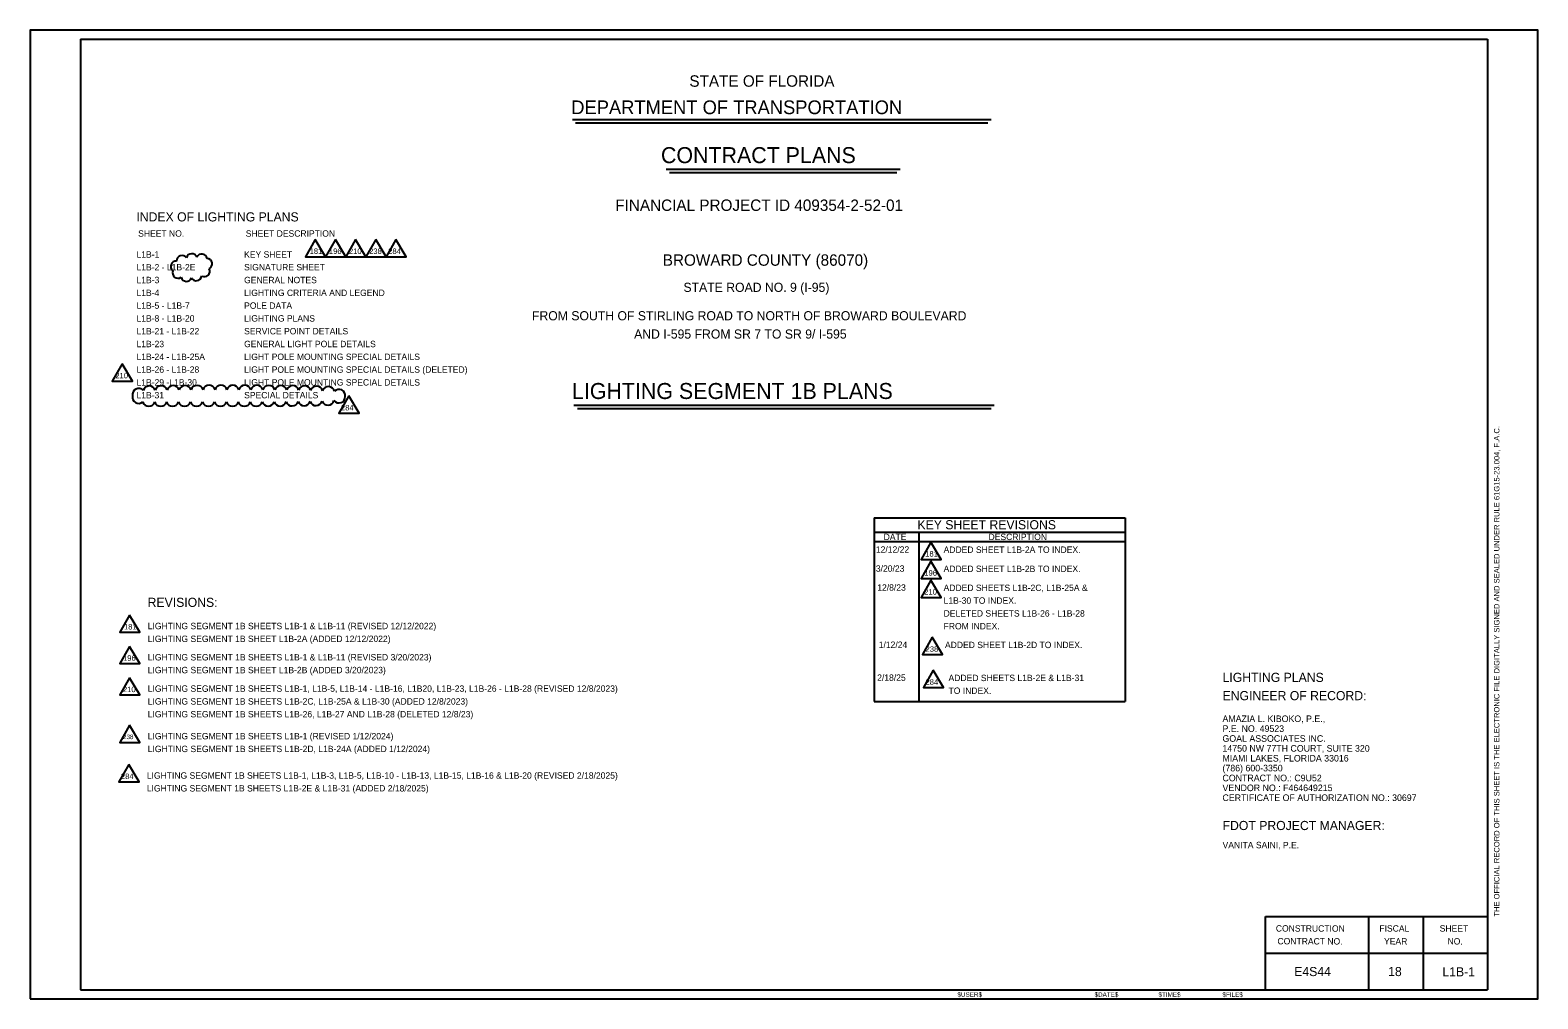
# Model space of a CAD drawing. Extents: x -818.6 to -802.1, y -2197.9 to -2175.
# Drawn here: x -818.56 to -802.06, y -2197.92 to -2187.32 of the extents above; entities that cross this region are included whole.
import ezdxf

# ---------------------------------------------------------------- set-up
doc = ezdxf.new("R2010")
doc.units = 0
for name, color, linetype in [('ActivePointCell_dp', 7, 'Continuous'), ('Cloud_dp', 7, 'Continuous'), ('PlotBorder_dp', 7, 'Continuous'), ('SheetBorder_dp', 7, 'Continuous'), ('SheetLines_dp', 7, 'Continuous'), ('SumBoxLines_dp', 7, 'Continuous'), ('TextLabel', 7, 'Continuous'), ('TextMinor', 7, 'Continuous'), ('TextMisc', 7, 'Continuous'), ('TextNotes', 7, 'Continuous'), ('TextShtNo', 7, 'Continuous'), ('TextTitle', 7, 'Continuous')]:
    doc.layers.add(name, color=color, linetype=linetype)

msp = doc.modelspace()

# ---------------------------------------------------------------- linework, layer by layer
at = {"layer": 'ActivePointCell_dp'}
msp.add_line((-802.614, -2187.419), (-802.614, -2187.419), dxfattribs=at)
at = {"layer": 'Cloud_dp'}
for points in [[(-815.443, -2189.61), (-815.551, -2189.798), (-815.33, -2189.798)], [(-815.222, -2189.61), (-815.33, -2189.798), (-815.109, -2189.798)], [(-815.002, -2189.61), (-815.109, -2189.798), (-814.889, -2189.798)], [(-814.781, -2189.61), (-814.889, -2189.798), (-814.668, -2189.798)], [(-814.56, -2189.61), (-814.667, -2189.798), (-814.447, -2189.798)], [(-817.558, -2190.971), (-817.666, -2191.159), (-817.445, -2191.159)], [(-815.076, -2191.322), (-815.184, -2191.51), (-814.963, -2191.51)], [(-808.706, -2192.922), (-808.814, -2193.11), (-808.593, -2193.11)], [(-808.706, -2193.13), (-808.814, -2193.318), (-808.593, -2193.318)], [(-808.706, -2193.338), (-808.814, -2193.526), (-808.593, -2193.526)], [(-817.475, -2193.719), (-817.583, -2193.907), (-817.362, -2193.907)], [(-808.691, -2193.963), (-808.799, -2194.151), (-808.578, -2194.151)], [(-817.475, -2194.062), (-817.583, -2194.25), (-817.362, -2194.25)], [(-808.68, -2194.324), (-808.787, -2194.512), (-808.567, -2194.512)], [(-817.475, -2194.405), (-817.583, -2194.593), (-817.362, -2194.593)], [(-817.475, -2194.924), (-817.583, -2195.113), (-817.362, -2195.113)], [(-817.485, -2195.356), (-817.593, -2195.544), (-817.372, -2195.544)]]:
    msp.add_lwpolyline(points, close=True, dxfattribs=at)
for centre, radius, start, end in [((-816.966, -2189.905), 0.0599, 86.9907, 231.9907), ((-816.902, -2189.845), 0.06, 35.4166, 180.4166), ((-816.795, -2189.825), 0.0599, 21.2778, 166.2778), ((-816.685, -2189.828), 0.0599, 9.9863, 154.9863), ((-816.632, -2189.877), 0.0599, 298.9542, 83.9542), ((-816.946, -2189.974), 0.0599, 159.4236, 304.4236), ((-816.854, -2190.008), 0.0599, 194.4381, 339.4381), ((-816.745, -2190.001), 0.0599, 207.5787, 352.5787), ((-816.657, -2189.957), 0.0599, 241.4449, 26.4449), ((-817.377, -2191.335), 0.0686, 166.4751, 311.4751), ((-817.376, -2191.309), 0.0686, 43.0695, 188.0695), ((-817.26, -2191.281), 0.0686, 19.0384, 164.0384), ((-817.129, -2191.278), 0.0686, 18.4168, 163.4168), ((-816.999, -2191.277), 0.0686, 18.1078, 163.1078), ((-816.868, -2191.276), 0.0686, 17.9137, 162.9137), ((-816.737, -2191.275), 0.0686, 17.7772, 162.7772), ((-816.606, -2191.274), 0.0686, 17.6744, 162.6744), ((-816.475, -2191.274), 0.0686, 17.5934, 162.5934), ((-816.345, -2191.274), 0.0686, 17.5274, 162.5274), ((-816.214, -2191.274), 0.0686, 17.4419, 162.4419), ((-816.083, -2191.274), 0.0686, 17.3173, 162.3173), ((-815.952, -2191.275), 0.0686, 17.164, 162.164), ((-815.821, -2191.276), 0.0686, 16.9692, 161.9692), ((-815.691, -2191.277), 0.0686, 16.7096, 161.7096), ((-815.56, -2191.279), 0.0686, 16.3389, 161.3389), ((-815.429, -2191.283), 0.0686, 15.744, 160.744), ((-815.299, -2191.288), 0.0686, 14.5241, 159.5241), ((-815.184, -2191.33), 0.0687, 217.023, 2.023), ((-815.183, -2191.318), 0.0685, 351.6834, 136.6834), ((-817.266, -2191.366), 0.0686, 197.5, 342.5), ((-817.135, -2191.366), 0.0686, 197.5, 342.5), ((-817.005, -2191.366), 0.0686, 197.5, 342.5), ((-816.874, -2191.366), 0.0686, 197.5, 342.5), ((-816.743, -2191.366), 0.0686, 197.5, 342.5), ((-816.612, -2191.366), 0.0686, 197.5, 342.5), ((-816.481, -2191.366), 0.0686, 197.5, 342.5), ((-816.35, -2191.366), 0.0686, 197.5, 342.5), ((-816.22, -2191.366), 0.0686, 197.5078, 342.5078), ((-816.089, -2191.366), 0.0686, 197.6006, 342.6006), ((-815.958, -2191.365), 0.0686, 197.7378, 342.7378), ((-815.827, -2191.364), 0.0686, 197.9119, 342.9119), ((-815.696, -2191.363), 0.0686, 198.1433, 343.1433), ((-815.566, -2191.361), 0.0686, 198.4725, 343.4725), ((-815.435, -2191.359), 0.0686, 198.9973, 343.9973), ((-815.305, -2191.354), 0.0686, 200.0559, 345.0559)]:
    msp.add_arc(centre, radius, start, end, dxfattribs=at)
at = {"layer": 'PlotBorder_dp'}
msp.add_lwpolyline([(-818.564, -2197.919), (-802.064, -2197.919), (-802.064, -2187.319), (-818.564, -2187.319)], close=True, dxfattribs=at)
at = {"layer": 'SheetBorder_dp'}
for p, q in [((-818.014, -2187.419), (-818.014, -2197.819)), ((-818.014, -2187.419), (-802.614, -2187.419)), ((-802.614, -2187.419), (-802.614, -2197.819)), ((-818.014, -2197.819), (-802.614, -2197.819))]:
    msp.add_line(p, q, dxfattribs=at)
at = {"layer": 'SheetLines_dp'}
for p, q in [((-805.044, -2197.019), (-802.614, -2197.019)), ((-805.044, -2197.819), (-805.044, -2197.019)), ((-803.914, -2197.819), (-803.914, -2197.019)), ((-803.314, -2197.819), (-803.314, -2197.019)), ((-805.044, -2197.419), (-802.614, -2197.419))]:
    msp.add_line(p, q, dxfattribs=at)
at = {"layer": 'SumBoxLines_dp'}
for p, q in [((-809.327, -2192.654), (-809.327, -2194.666)), ((-809.327, -2192.654), (-806.58, -2192.654)), ((-806.58, -2192.654), (-806.58, -2194.666)), ((-809.327, -2192.814), (-806.58, -2192.814)), ((-808.837, -2192.814), (-808.837, -2194.666)), ((-809.327, -2192.914), (-806.58, -2192.914)), ((-809.327, -2194.666), (-806.58, -2194.666))]:
    msp.add_line(p, q, dxfattribs=at)
at = {"layer": 'TextTitle'}
for p, q in [((-812.63, -2188.295), (-808.048, -2188.295)), ((-812.597, -2188.333), (-808.083, -2188.333)), ((-811.605, -2188.84), (-809.044, -2188.84)), ((-811.566, -2188.878), (-809.077, -2188.878)), ((-812.614, -2191.421), (-808.015, -2191.421)), ((-812.575, -2191.459), (-808.047, -2191.459))]:
    msp.add_line(p, q, dxfattribs=at)

# ---------------------------------------------------------------- texts
at = {"layer": 'Cloud_dp'}
for s, height, p in [('181', 0.06, (-815.505, -2189.768)), ('196', 0.06, (-815.294, -2189.768)), ('210', 0.06, (-815.075, -2189.768)), ('238', 0.06, (-814.854, -2189.768)), ('284', 0.06, (-814.645, -2189.768)), ('210', 0.06, (-817.631, -2191.129)), ('284', 0.06, (-815.162, -2191.48)), ('181', 0.06, (-808.768, -2193.079)), ('196', 0.06, (-808.778, -2193.288)), ('210', 0.06, (-808.779, -2193.496)), ('181', 0.06, (-817.537, -2193.877)), ('196', 0.06, (-817.547, -2194.22)), ('238', 0.06, (-808.764, -2194.121)), ('284', 0.06, (-808.765, -2194.482)), ('210', 0.06, (-817.548, -2194.563)), ('238', 0.05, (-817.548, -2195.077)), ('284', 0.06, (-817.57, -2195.514))]:
    msp.add_text(s, height=height, rotation=0, dxfattribs=at).set_placement(p)
at = {"layer": 'TextLabel'}
for s, height, p in [('FINANCIAL PROJECT ID 409354-2-52-01', 0.125, (-812.16, -2189.297)), ('INDEX OF LIGHTING PLANS', 0.1, (-817.401, -2189.412)), ('L1B-1', 0.07, (-817.4, -2189.808)), ('L1B-2 - L1B-2E', 0.07, (-817.4, -2189.948)), ('SIGNATURE SHEET', 0.07, (-816.222, -2189.948)), ('KEY SHEET', 0.07, (-816.222, -2189.808)), ('BROWARD COUNTY (86070)', 0.125, (-811.64, -2189.897)), ('L1B-3', 0.07, (-817.4, -2190.088)), ('GENERAL NOTES', 0.07, (-816.222, -2190.088)), ('L1B-4', 0.07, (-817.4, -2190.228)), ('LIGHTING CRITERIA AND LEGEND', 0.07, (-816.222, -2190.228)), ('STATE ROAD NO. 9 (I-95)', 0.1, (-811.414, -2190.183)), ('L1B-5 - L1B-7', 0.07, (-817.4, -2190.368)), ('POLE DATA', 0.07, (-816.222, -2190.368)), ('L1B-8 - L1B-20', 0.07, (-817.4, -2190.508)), ('LIGHTING PLANS', 0.07, (-816.222, -2190.508)), ('FROM SOUTH OF STIRLING ROAD TO NORTH OF BROWARD BOULEVARD', 0.1, (-813.072, -2190.494)), ('L1B-21 - L1B-22', 0.07, (-817.4, -2190.648)), ('SERVICE POINT DETAILS', 0.07, (-816.222, -2190.648)), ('AND I-595 FROM SR 7 TO SR 9/ I-595', 0.1, (-811.954, -2190.694)), ('L1B-23', 0.07, (-817.4, -2190.788)), ('L1B-24 - L1B-25A', 0.07, (-817.4, -2190.928)), ('GENERAL LIGHT POLE DETAILS', 0.07, (-816.222, -2190.788)), ('LIGHT POLE MOUNTING SPECIAL DETAILS', 0.07, (-816.222, -2190.928)), ('L1B-26 - L1B-28', 0.07, (-817.4, -2191.068)), ('LIGHT POLE MOUNTING SPECIAL DETAILS (DELETED)', 0.07, (-816.222, -2191.068)), ('L1B-29 -L1B-30', 0.07, (-817.4, -2191.208)), ('LIGHT POLE MOUNTING SPECIAL DETAILS', 0.07, (-816.222, -2191.208)), ('L1B-31', 0.07, (-817.4, -2191.348)), ('SPECIAL DETAILS', 0.07, (-816.222, -2191.348)), ('KEY SHEET REVISIONS', 0.1, (-808.853, -2192.781)), ('REVISIONS:', 0.1, (-817.278, -2193.63)), ('LIGHTING PLANS', 0.1, (-805.514, -2194.451)), ('ENGINEER OF RECORD:', 0.1, (-805.514, -2194.651)), ('AMAZIA L. KIBOKO, P.E.,', 0.07202, (-805.515, -2194.89)), ('P.E. NO. 49523', 0.07202, (-805.515, -2194.998)), ('GOAL ASSOCIATES INC. ', 0.07202, (-805.515, -2195.106)), ('14750 NW 77TH COURT, SUITE 320', 0.07202, (-805.515, -2195.214)), ('MIAMI LAKES, FLORIDA 33016', 0.07202, (-805.515, -2195.322)), ('CONTRACT NO.: C9U52', 0.07202, (-805.515, -2195.538)), ('(786) 600-3350', 0.07202, (-805.515, -2195.43)), ('VENDOR NO.: F464649215', 0.07202, (-805.515, -2195.646)), ('CERTIFICATE OF AUTHORIZATION NO.: 30697', 0.07202, (-805.515, -2195.754)), ('E4S44', 0.1, (-804.73, -2197.67)), ('18', 0.1, (-803.702, -2197.67))]:
    msp.add_text(s, height=height, dxfattribs=at).set_placement(p)
at = {"layer": 'TextMinor'}
for s, height, p in [('12/12/22', 0.07, (-809.308, -2193.037)), ('ADDED SHEET L1B-2A TO INDEX.', 0.07, (-808.567, -2193.039)), ('3/20/23', 0.07, (-809.308, -2193.245)), ('ADDED SHEET L1B-2B TO INDEX.', 0.07, (-808.567, -2193.248)), ('12/8/23', 0.07, (-809.293, -2193.453)), ('ADDED SHEETS L1B-2C, L1B-25A & ', 0.07, (-808.567, -2193.456)), ('L1B-30 TO INDEX.', 0.07, (-808.567, -2193.596)), ('DELETED SHEETS L1B-26 - L1B-28 ', 0.07, (-808.567, -2193.736)), ('FROM INDEX.', 0.07, (-808.567, -2193.876)), ('1/12/24', 0.07, (-809.277, -2194.079)), ('ADDED SHEET L1B-2D TO INDEX.', 0.07, (-808.552, -2194.081)), ('2/18/25', 0.07, (-809.294, -2194.439)), ('ADDED SHEETS L1B-2E & L1B-31   ', 0.07, (-808.513, -2194.442)), ('TO INDEX.', 0.07, (-808.513, -2194.582)), ('$USER$', 0.05, (-808.415, -2197.897))]:
    msp.add_text(s, height=height, dxfattribs=at).set_placement(p)
for s, p in [('$DATE$', (-806.915, -2197.897)), ('$TIME$', (-806.215, -2197.897)), ('$FILE$', (-805.515, -2197.897))]:
    msp.add_text(s, height=0.05, rotation=360, dxfattribs=at).set_placement(p)
at = {"layer": 'TextMisc'}
msp.add_text('THE OFFICIAL RECORD OF THIS SHEET IS THE ELECTRONIC FILE DIGITALLY SIGNED AND SEALED UNDER RULE 61G15-23.004, F.A.C.', height=0.06, rotation=90, dxfattribs=at).set_placement((-802.484, -2197.019))
at = {"layer": 'TextNotes'}
for s, height, p in [('SHEET NO.', 0.07, (-817.382, -2189.579)), ('SHEET DESCRIPTION', 0.07, (-816.204, -2189.579)), ('DATE', 0.07, (-809.223, -2192.899)), ('DESCRIPTION', 0.07, (-808.075, -2192.899)), ('LIGHTING SEGMENT 1B SHEETS L1B-1 & L1B-11 (REVISED 12/12/2022)', 0.06998, (-817.277, -2193.874)), ('LIGHTING SEGMENT 1B SHEET L1B-2A (ADDED 12/12/2022)', 0.06998, (-817.277, -2194.014)), ('LIGHTING SEGMENT 1B SHEETS L1B-1 & L1B-11 (REVISED 3/20/2023)', 0.06998, (-817.277, -2194.216)), ('LIGHTING SEGMENT 1B SHEET L1B-2B (ADDED 3/20/2023)', 0.06998, (-817.277, -2194.356)), ('LIGHTING SEGMENT 1B SHEETS L1B-1, L1B-5, L1B-14 - L1B-16, L1B20, L1B-23, L1B-26 - L1B-28 (REVISED 12/8/2023)', 0.069982, (-817.277, -2194.559)), ('LIGHTING SEGMENT 1B SHEETS L1B-2C, L1B-25A & L1B-30 (ADDED 12/8/2023)', 0.06998, (-817.277, -2194.699)), ('LIGHTING SEGMENT 1B SHEETS L1B-26, L1B-27 AND L1B-28 (DELETED 12/8/23)', 0.06998, (-817.277, -2194.839)), ('LIGHTING SEGMENT 1B SHEETS L1B-1 (REVISED 1/12/2024)', 0.06998, (-817.277, -2195.079)), ('LIGHTING SEGMENT 1B SHEETS L1B-2D, L1B-24A (ADDED 1/12/2024)', 0.06998, (-817.277, -2195.219)), ('LIGHTING SEGMENT 1B SHEETS L1B-1, L1B-3, L1B-5, L1B-10 - L1B-13, L1B-15, L1B-16 & L1B-20 (REVISED 2/18/2025)', 0.069982, (-817.287, -2195.51)), ('LIGHTING SEGMENT 1B SHEETS L1B-2E & L1B-31 (ADDED 2/18/2025)', 0.06998, (-817.287, -2195.65)), ('FDOT PROJECT MANAGER:', 0.1, (-805.514, -2196.072)), ('VANITA SAINI, P.E.', 0.07, (-805.514, -2196.271))]:
    msp.add_text(s, height=height, dxfattribs=at).set_placement(p)
for s, p in [('CONSTRUCTION', (-804.931, -2197.183)), ('FISCAL', (-803.798, -2197.183)), ('SHEET', (-803.138, -2197.183)), ('CONTRACT NO.', (-804.913, -2197.323)), ('YEAR', (-803.747, -2197.324)), ('NO.', (-803.052, -2197.324))]:
    msp.add_text(s, height=0.07, rotation=359.8607, dxfattribs=at).set_placement(p)
at = {"layer": 'TextShtNo'}
msp.add_text('L1B-1', height=0.1, dxfattribs=at).set_placement((-803.108, -2197.673))
at = {"layer": 'TextTitle'}
for s, height, p in [('STATE OF FLORIDA', 0.125, (-811.349, -2187.938)), ('DEPARTMENT OF TRANSPORTATION', 0.15, (-812.642, -2188.238)), ('CONTRACT PLANS', 0.175, (-811.66, -2188.774)), ('LIGHTING SEGMENT 1B PLANS', 0.175, (-812.634, -2191.355))]:
    msp.add_text(s, height=height, dxfattribs=at).set_placement(p)

doc.saveas('drawing.dxf')
